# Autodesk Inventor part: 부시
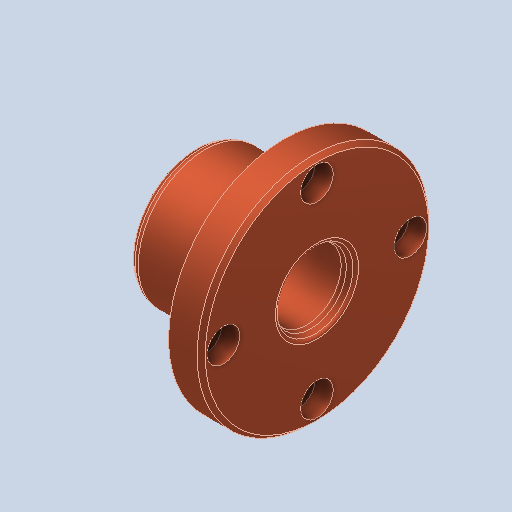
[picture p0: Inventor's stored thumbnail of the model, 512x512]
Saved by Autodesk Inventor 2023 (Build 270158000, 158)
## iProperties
Created: 2024-09
Part Number: 부시
Material: 구리, 합금
Document SubType Name: Modeling
Designer: asung
Density: 8.92 g/cm^3
Appearance: 기본값
Author: jhkim
Sending System: Autodesk Inventor 2025
Preprocessor: ST-DEVELOPER v20
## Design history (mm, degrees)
feature "솔리드1"
node "솔리드2"
